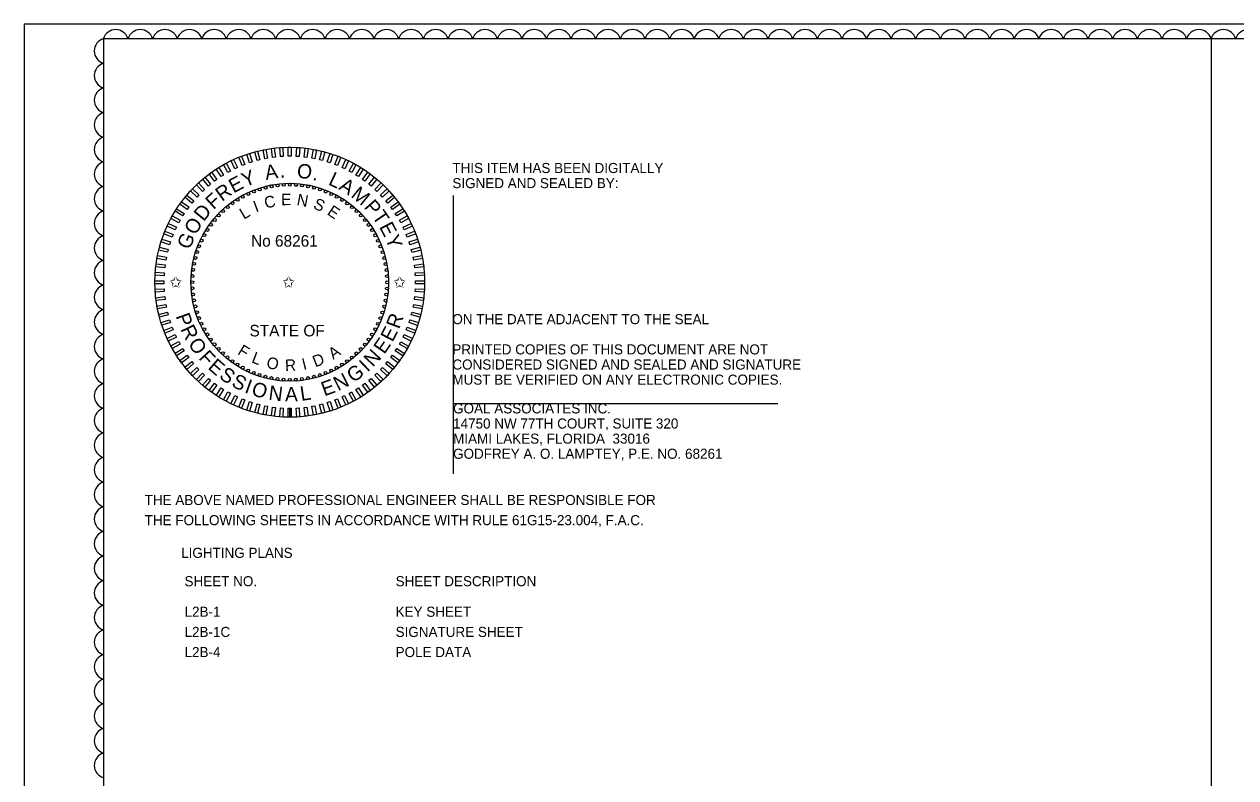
# Model space of a CAD drawing. Extents: x -811.3 to -790.1, y -2211.9 to -2188.9.
# Drawn here: x -811.34 to -802.91, y -2206.57 to -2201.34 of the extents above; entities that cross this region are included whole.
import ezdxf

# ---------------------------------------------------------------- set-up
doc = ezdxf.new("R2010")
doc.units = 0
for name, color, linetype in [('Cloud_dp', 7, 'Continuous'), ('Logo_dp', 7, 'Continuous'), ('NonPlottingEle_dp', 7, 'Continuous'), ('PlotBorder_dp', 7, 'Continuous'), ('ScratchEle_dp', 7, 'Continuous'), ('SheetBorder_dp', 7, 'Continuous'), ('TextMisc', 7, 'Continuous'), ('TextNotes', 7, 'Continuous')]:
    doc.layers.add(name, color=color, linetype=linetype)

msp = doc.modelspace()

# ---------------------------------------------------------------- linework, layer by layer
at = {"layer": 'Cloud_dp'}
for centre, start, end in [((-810.7002, -2201.467), 17.5, 162.5), ((-810.5291, -2201.467), 17.5, 162.5), ((-810.358, -2201.467), 17.5, 162.5), ((-810.1868, -2201.467), 17.5, 162.5), ((-810.0157, -2201.467), 17.5, 162.5), ((-809.8446, -2201.467), 17.5, 162.5), ((-809.6735, -2201.467), 17.5, 162.5), ((-809.5024, -2201.467), 17.5, 162.5), ((-809.3312, -2201.467), 17.5, 162.5), ((-809.1601, -2201.467), 17.5, 162.5), ((-808.989, -2201.467), 17.5, 162.5), ((-808.8179, -2201.467), 17.5, 162.5), ((-808.6467, -2201.467), 17.5, 162.5), ((-808.4756, -2201.467), 17.5, 162.5), ((-808.3045, -2201.467), 17.5, 162.5), ((-808.1334, -2201.467), 17.5, 162.5), ((-807.9622, -2201.467), 17.5, 162.5), ((-807.7911, -2201.467), 17.5, 162.5), ((-807.62, -2201.467), 17.5, 162.5), ((-807.4489, -2201.467), 17.5, 162.5), ((-807.2778, -2201.467), 17.5, 162.5), ((-807.1066, -2201.467), 17.5, 162.5), ((-806.9355, -2201.467), 17.5, 162.5), ((-806.7644, -2201.467), 17.5, 162.5), ((-806.5933, -2201.467), 17.5, 162.5), ((-806.4221, -2201.467), 17.5, 162.5), ((-806.251, -2201.467), 17.5, 162.5), ((-806.0799, -2201.467), 17.5, 162.5), ((-805.9088, -2201.467), 17.5, 162.5), ((-805.7377, -2201.467), 17.5, 162.5), ((-805.5665, -2201.467), 17.5, 162.5), ((-805.3954, -2201.467), 17.5, 162.5), ((-805.2243, -2201.467), 17.5, 162.5), ((-805.0532, -2201.467), 17.5, 162.5), ((-804.882, -2201.467), 17.5, 162.5), ((-804.7109, -2201.467), 17.5, 162.5), ((-804.5398, -2201.467), 17.5, 162.5), ((-804.3687, -2201.467), 17.5, 162.5), ((-804.1976, -2201.467), 17.5, 162.5), ((-804.0264, -2201.467), 17.5, 162.5), ((-803.8553, -2201.467), 17.5, 162.5), ((-803.6842, -2201.467), 17.5, 162.5), ((-803.5131, -2201.467), 17.5, 162.5), ((-803.3419, -2201.467), 17.5, 162.5), ((-803.1708, -2201.467), 17.5, 162.5), ((-802.9997, -2201.467), 17.5, 162.5), ((-802.8286, -2201.467), 17.5, 162.5), ((-810.7588, -2201.5256), 107.5, 252.5), ((-810.7588, -2201.6967), 107.5, 252.5), ((-810.7588, -2201.8679), 107.5, 252.5), ((-810.7588, -2202.039), 107.5, 252.5), ((-810.7588, -2202.2101), 107.5, 252.5), ((-810.7588, -2202.3812), 107.5, 252.5), ((-810.7588, -2202.5523), 107.5, 252.5), ((-810.7588, -2202.7235), 107.5, 252.5), ((-810.7588, -2202.8946), 107.5, 252.5), ((-810.7588, -2203.0657), 107.5, 252.5), ((-810.7588, -2203.2368), 107.5, 252.5), ((-810.7588, -2203.408), 107.5, 252.5), ((-810.7588, -2203.5791), 107.5, 252.5), ((-810.7588, -2203.7502), 107.5, 252.5), ((-810.7588, -2203.9213), 107.5, 252.5), ((-810.7588, -2204.0924), 107.5, 252.5), ((-810.7588, -2204.2636), 107.5, 252.5), ((-810.7588, -2204.4347), 107.5, 252.5), ((-810.7588, -2204.6058), 107.5, 252.5), ((-810.7588, -2204.7769), 107.5, 252.5), ((-810.7588, -2204.9481), 107.5, 252.5), ((-810.7588, -2205.1192), 107.5, 252.5), ((-810.7588, -2205.2903), 107.5, 252.5), ((-810.7588, -2205.4614), 107.5, 252.5), ((-810.7588, -2205.6326), 107.5, 252.5), ((-810.7588, -2205.8037), 107.5, 252.5), ((-810.7588, -2205.9748), 107.5, 252.5), ((-810.7588, -2206.1459), 107.5, 252.5), ((-810.7588, -2206.317), 107.5, 252.5), ((-810.7588, -2206.4882), 107.5, 252.5)]:
    msp.add_arc(centre, 0.0897, start, end, dxfattribs=at)
at = {"layer": 'Logo_dp'}
for p, q in [((-809.5001, -2204.0695), (-809.5003, -2204.007)), ((-809.4901, -2204.0695), (-809.4903, -2204.007)), ((-809.4801, -2204.0695), (-809.4803, -2204.007))]:
    msp.add_line(p, q, dxfattribs=at)
for points in [[(-809.8028, -2202.3147), (-809.8215, -2202.3221), (-809.8445, -2202.2641), (-809.8258, -2202.2566)], [(-809.7508, -2202.2967), (-809.77, -2202.3029), (-809.7893, -2202.2435), (-809.7701, -2202.2373)], [(-809.6979, -2202.2819), (-809.7174, -2202.287), (-809.7329, -2202.2265), (-809.7134, -2202.2215)], [(-809.6441, -2202.2706), (-809.6639, -2202.2743), (-809.6756, -2202.213), (-809.6558, -2202.2092)], [(-809.5897, -2202.2626), (-809.6097, -2202.2651), (-809.6175, -2202.2032), (-809.5975, -2202.2007)], [(-809.5349, -2202.2581), (-809.555, -2202.2593), (-809.559, -2202.197), (-809.5388, -2202.1957)], [(-809.4799, -2202.257), (-809.5001, -2202.257), (-809.5001, -2202.1945), (-809.4799, -2202.1945)], [(-809.425, -2202.2593), (-809.4452, -2202.2581), (-809.4412, -2202.1958), (-809.4211, -2202.197)], [(-809.3703, -2202.2652), (-809.3904, -2202.2626), (-809.3825, -2202.2007), (-809.3625, -2202.2032)], [(-809.3162, -2202.2744), (-809.336, -2202.2706), (-809.3243, -2202.2093), (-809.3045, -2202.2131)], [(-809.2626, -2202.287), (-809.2822, -2202.282), (-809.2667, -2202.2215), (-809.2471, -2202.2265)], [(-809.21, -2202.303), (-809.2292, -2202.2967), (-809.2099, -2202.2373), (-809.1907, -2202.2436)], [(-809.1585, -2202.3222), (-809.1773, -2202.3147), (-809.1543, -2202.2567), (-809.1355, -2202.2641)], [(-809.9504, -2202.3877), (-809.9674, -2202.3986), (-810.0009, -2202.3458), (-809.9838, -2202.335)], [(-809.9027, -2202.3603), (-809.9204, -2202.37), (-809.9505, -2202.3153), (-809.9328, -2202.3056)], [(-809.8535, -2202.3359), (-809.8717, -2202.3445), (-809.8983, -2202.288), (-809.8801, -2202.2794)], [(-809.1083, -2202.3446), (-809.1266, -2202.336), (-809.1, -2202.2795), (-809.0817, -2202.2881)], [(-809.0596, -2202.3701), (-809.0773, -2202.3604), (-809.0473, -2202.3057), (-809.0296, -2202.3154)], [(-809.0127, -2202.3987), (-809.0297, -2202.3878), (-808.9962, -2202.3351), (-808.9792, -2202.3459)], [(-810.04, -2202.4513), (-810.0556, -2202.4642), (-810.0954, -2202.416), (-810.0798, -2202.4032)], [(-809.9962, -2202.4181), (-810.0125, -2202.43), (-810.0492, -2202.3795), (-810.0329, -2202.3676)], [(-808.9676, -2202.4301), (-808.9839, -2202.4182), (-808.9472, -2202.3677), (-808.9308, -2202.3796)], [(-808.9245, -2202.4643), (-808.9401, -2202.4514), (-808.9003, -2202.4033), (-808.8847, -2202.4162)], [(-810.121, -2202.5256), (-810.1348, -2202.5403), (-810.1804, -2202.4976), (-810.1665, -2202.4828)], [(-810.0817, -2202.4872), (-810.0964, -2202.501), (-810.1392, -2202.4555), (-810.1244, -2202.4416)], [(-808.8837, -2202.5011), (-808.8984, -2202.4873), (-808.8557, -2202.4418), (-808.841, -2202.4556)], [(-808.8453, -2202.5404), (-808.8591, -2202.5257), (-808.8136, -2202.483), (-808.7998, -2202.4977)], [(-810.192, -2202.6094), (-810.2039, -2202.6258), (-810.2544, -2202.5891), (-810.2426, -2202.5727)], [(-810.1579, -2202.5664), (-810.1707, -2202.5819), (-810.2188, -2202.5421), (-810.206, -2202.5266)], [(-808.8094, -2202.5821), (-808.8223, -2202.5665), (-808.7742, -2202.5267), (-808.7613, -2202.5423)], [(-808.7762, -2202.6259), (-808.7881, -2202.6096), (-808.7376, -2202.5729), (-808.7257, -2202.5892)], [(-810.252, -2202.7015), (-810.2617, -2202.7192), (-810.3164, -2202.6891), (-810.3067, -2202.6715)], [(-810.2235, -2202.6545), (-810.2343, -2202.6716), (-810.287, -2202.6381), (-810.2762, -2202.6211)], [(-808.7459, -2202.6717), (-808.7567, -2202.6547), (-808.7039, -2202.6212), (-808.6931, -2202.6383)], [(-808.7184, -2202.7194), (-808.7281, -2202.7017), (-808.6734, -2202.6716), (-808.6637, -2202.6893)], [(-810.2775, -2202.7502), (-810.2861, -2202.7685), (-810.3426, -2202.7419), (-810.334, -2202.7236)], [(-808.694, -2202.7687), (-808.7026, -2202.7504), (-808.6461, -2202.7238), (-808.6375, -2202.7421)], [(-810.3192, -2202.8519), (-810.3254, -2202.8711), (-810.3848, -2202.8518), (-810.3786, -2202.8326)], [(-810.3, -2202.8004), (-810.3074, -2202.8192), (-810.3654, -2202.7962), (-810.358, -2202.7774)], [(-808.6728, -2202.8194), (-808.6802, -2202.8006), (-808.6222, -2202.7776), (-808.6147, -2202.7964)], [(-808.6548, -2202.8713), (-808.661, -2202.8521), (-808.6016, -2202.8328), (-808.5954, -2202.852)], [(-810.3351, -2202.9045), (-810.3401, -2202.9241), (-810.4006, -2202.9086), (-810.3956, -2202.889)], [(-808.64, -2202.9243), (-808.6451, -2202.9047), (-808.5846, -2202.8892), (-808.5796, -2202.9087)], [(-810.357, -2203.0122), (-810.3595, -2203.0323), (-810.4215, -2203.0244), (-810.4189, -2203.0044)], [(-810.3477, -2202.958), (-810.3515, -2202.9779), (-810.4129, -2202.9662), (-810.4091, -2202.9463)], [(-808.6287, -2202.978), (-808.6325, -2202.9582), (-808.5711, -2202.9465), (-808.5673, -2202.9663)], [(-808.6207, -2203.0324), (-808.6232, -2203.0124), (-808.5613, -2203.0046), (-808.5588, -2203.0246)], [(-810.3628, -2203.0669), (-810.3641, -2203.087), (-810.4264, -2203.0831), (-810.4251, -2203.063)], [(-808.6162, -2203.0872), (-808.6174, -2203.0671), (-808.5551, -2203.0632), (-808.5539, -2203.0833)], [(-810.3652, -2203.1218), (-810.3652, -2203.142), (-810.4276, -2203.142), (-810.4276, -2203.1218)], [(-810.3641, -2203.1768), (-810.3628, -2203.1969), (-810.4251, -2203.2009), (-810.4264, -2203.1807)], [(-808.6175, -2203.1971), (-808.6162, -2203.177), (-808.5539, -2203.1809), (-808.5551, -2203.201)], [(-808.6151, -2203.1422), (-808.6151, -2203.122), (-808.5527, -2203.122), (-808.5527, -2203.1422)], [(-810.3595, -2203.2316), (-810.357, -2203.2516), (-810.4189, -2203.2594), (-810.4215, -2203.2394)], [(-808.6233, -2203.2518), (-808.6207, -2203.2318), (-808.5588, -2203.2396), (-808.5613, -2203.2596)], [(-810.3516, -2203.286), (-810.3478, -2203.3058), (-810.4091, -2203.3175), (-810.4129, -2203.2977)], [(-810.3402, -2203.3398), (-810.3352, -2203.3593), (-810.3957, -2203.3748), (-810.4007, -2203.3553)], [(-808.6451, -2203.3595), (-808.6401, -2203.3399), (-808.5796, -2203.3555), (-808.5846, -2203.375)], [(-808.6325, -2203.306), (-808.6287, -2203.2861), (-808.5674, -2203.2978), (-808.5712, -2203.3177)], [(-810.3255, -2203.3927), (-810.3192, -2203.4119), (-810.3786, -2203.4312), (-810.3849, -2203.412)], [(-808.6611, -2203.4121), (-808.6548, -2203.3929), (-808.5954, -2203.4122), (-808.6017, -2203.4314)], [(-810.3075, -2203.4447), (-810.3, -2203.4634), (-810.3581, -2203.4864), (-810.3655, -2203.4676)], [(-810.2862, -2203.4954), (-810.2776, -2203.5136), (-810.3341, -2203.5402), (-810.3427, -2203.5219)], [(-808.7027, -2203.5138), (-808.6941, -2203.4955), (-808.6376, -2203.5221), (-808.6462, -2203.5404)], [(-808.6803, -2203.4636), (-808.6729, -2203.4448), (-808.6148, -2203.4678), (-808.6222, -2203.4866)], [(-810.2618, -2203.5446), (-810.2521, -2203.5623), (-810.3068, -2203.5924), (-810.3165, -2203.5747)], [(-810.2344, -2203.5923), (-810.2236, -2203.6093), (-810.2763, -2203.6428), (-810.2871, -2203.6257)], [(-808.7568, -2203.6095), (-808.746, -2203.5924), (-808.6932, -2203.6259), (-808.704, -2203.6429)], [(-808.7282, -2203.5625), (-808.7185, -2203.5448), (-808.6638, -2203.5749), (-808.6735, -2203.5926)], [(-810.204, -2203.6381), (-810.1922, -2203.6544), (-810.2427, -2203.6911), (-810.2545, -2203.6748)], [(-810.1708, -2203.6819), (-810.158, -2203.6975), (-810.2061, -2203.7373), (-810.2189, -2203.7217)], [(-808.8224, -2203.6976), (-808.8095, -2203.6821), (-808.7614, -2203.7219), (-808.7743, -2203.7374)], [(-808.7882, -2203.6546), (-808.7763, -2203.6382), (-808.7258, -2203.6749), (-808.7377, -2203.6913)], [(-810.135, -2203.7236), (-810.1211, -2203.7383), (-810.1667, -2203.781), (-810.1805, -2203.7663)], [(-810.0965, -2203.7629), (-810.0818, -2203.7767), (-810.1246, -2203.8222), (-810.1393, -2203.8084)], [(-808.8985, -2203.7768), (-808.8838, -2203.763), (-808.8411, -2203.8085), (-808.8558, -2203.8224)], [(-808.8592, -2203.7384), (-808.8454, -2203.7237), (-808.7999, -2203.7665), (-808.8137, -2203.7812)], [(-810.0557, -2203.7997), (-810.0402, -2203.8126), (-810.08, -2203.8607), (-810.0955, -2203.8478)], [(-810.0127, -2203.8339), (-809.9964, -2203.8458), (-810.0331, -2203.8963), (-810.0494, -2203.8844)], [(-808.984, -2203.8459), (-808.9677, -2203.834), (-808.931, -2203.8846), (-808.9473, -2203.8964)], [(-808.9402, -2203.8127), (-808.9247, -2203.7999), (-808.8848, -2203.848), (-808.9004, -2203.8608)], [(-809.9676, -2203.8654), (-809.9505, -2203.8762), (-809.984, -2203.9289), (-810.001, -2203.9181)], [(-809.9206, -2203.8939), (-809.9029, -2203.9036), (-809.933, -2203.9583), (-809.9507, -2203.9486)], [(-809.8719, -2203.9194), (-809.8536, -2203.928), (-809.8802, -2203.9845), (-809.8985, -2203.9759)], [(-809.1268, -2203.9281), (-809.1085, -2203.9195), (-809.0819, -2203.976), (-809.1002, -2203.9846)], [(-809.0775, -2203.9037), (-809.0598, -2203.894), (-809.0297, -2203.9487), (-809.0474, -2203.9584)], [(-809.0299, -2203.8763), (-809.0128, -2203.8655), (-808.9794, -2203.9182), (-808.9964, -2203.929)], [(-809.8217, -2203.9418), (-809.8029, -2203.9493), (-809.8259, -2204.0073), (-809.8447, -2203.9999)], [(-809.7702, -2203.9611), (-809.751, -2203.9673), (-809.7703, -2204.0267), (-809.7895, -2204.0204)], [(-809.7176, -2203.977), (-809.698, -2203.982), (-809.7136, -2204.0425), (-809.7331, -2204.0375)], [(-809.6641, -2203.9896), (-809.6443, -2203.9934), (-809.656, -2204.0547), (-809.6758, -2204.051)], [(-809.6099, -2203.9989), (-809.5899, -2204.0014), (-809.5977, -2204.0633), (-809.6177, -2204.0608)], [(-809.5552, -2204.0047), (-809.5351, -2204.0059), (-809.539, -2204.0683), (-809.5592, -2204.067)], [(-809.5003, -2204.007), (-809.4801, -2204.007), (-809.4801, -2204.0695), (-809.5003, -2204.0695)], [(-809.4453, -2204.0059), (-809.4252, -2204.0047), (-809.4213, -2204.067), (-809.4414, -2204.0683)], [(-809.3906, -2204.0014), (-809.3705, -2203.9989), (-809.3627, -2204.0608), (-809.3827, -2204.0634)], [(-809.3362, -2203.9934), (-809.3163, -2203.9897), (-809.3046, -2204.051), (-809.3245, -2204.0548)], [(-809.2824, -2203.9821), (-809.2628, -2203.9771), (-809.2473, -2204.0375), (-809.2668, -2204.0426)], [(-809.2294, -2203.9674), (-809.2102, -2203.9611), (-809.1909, -2204.0205), (-809.2101, -2204.0267)], [(-809.1775, -2203.9493), (-809.1587, -2203.9419), (-809.1357, -2204), (-809.1545, -2204.0074)]]:
    msp.add_lwpolyline(points, close=True, dxfattribs=at)
for centre in [(-809.7781, -2202.5188), (-809.739, -2202.5019), (-809.6989, -2202.4875), (-809.6581, -2202.4757), (-809.6165, -2202.4664), (-809.5745, -2202.4598), (-809.5321, -2202.4558), (-809.4896, -2202.4545), (-809.447, -2202.4559), (-809.4047, -2202.46), (-809.3626, -2202.4666), (-809.3211, -2202.476), (-809.2802, -2202.4879), (-809.2402, -2202.5023), (-809.2012, -2202.5193), (-809.8879, -2202.5836), (-809.8527, -2202.5597), (-809.816, -2202.5381), (-809.1633, -2202.5386), (-809.1266, -2202.5603), (-809.0915, -2202.5843), (-809.9836, -2202.6678), (-809.9535, -2202.6378), (-809.9215, -2202.6096), (-809.0579, -2202.6104), (-809.026, -2202.6385), (-808.9959, -2202.6687), (-810.0618, -2202.7685), (-810.0379, -2202.7333), (-810.0118, -2202.6997), (-808.9678, -2202.7006), (-808.9417, -2202.7343), (-808.9178, -2202.7695), (-810.1029, -2202.843), (-810.0835, -2202.8051), (-808.8962, -2202.8061), (-808.8769, -2202.8441), (-810.1343, -2202.9221), (-810.1198, -2202.8821), (-808.86, -2202.8831), (-808.8456, -2202.9232), (-810.1555, -2203.0045), (-810.1462, -2202.963), (-808.8338, -2202.9641), (-808.8245, -2203.0056), (-810.1662, -2203.0889), (-810.1622, -2203.0465), (-808.8179, -2203.0477), (-808.814, -2203.09), (-810.1676, -2203.1314), (-810.1663, -2203.174), (-808.814, -2203.1751), (-808.8127, -2203.1326), (-810.1623, -2203.2164), (-810.1557, -2203.2584), (-808.8248, -2203.2595), (-808.8181, -2203.2175), (-810.1464, -2203.2999), (-810.1346, -2203.3408), (-808.846, -2203.3419), (-808.8341, -2203.301), (-810.1202, -2203.3809), (-810.1034, -2203.4199), (-808.8774, -2203.421), (-808.8604, -2203.3819), (-810.0841, -2203.4579), (-810.0624, -2203.4945), (-810.0385, -2203.5298), (-808.9184, -2203.4955), (-808.8967, -2203.4589), (-810.0125, -2203.5634), (-809.9844, -2203.5954), (-808.9967, -2203.5962), (-808.9685, -2203.5643), (-808.9424, -2203.5307), (-809.9543, -2203.6255), (-809.9224, -2203.6536), (-809.8888, -2203.6798), (-809.0924, -2203.6804), (-809.0587, -2203.6544), (-809.0268, -2203.6262), (-809.8536, -2203.7037), (-809.817, -2203.7254), (-809.7791, -2203.7448), (-809.74, -2203.7617), (-809.7, -2203.7761), (-809.2813, -2203.7765), (-809.2413, -2203.7621), (-809.2022, -2203.7452), (-809.1642, -2203.7259), (-809.1276, -2203.7043), (-809.6591, -2203.7881), (-809.6176, -2203.7974), (-809.5756, -2203.8041), (-809.5332, -2203.8081), (-809.4901, -2203.8095), (-809.4481, -2203.8082), (-809.4058, -2203.8042), (-809.3637, -2203.7976), (-809.3222, -2203.7883)]:
    msp.add_circle(centre, 0.01, dxfattribs=at)
at = {"layer": 'NonPlottingEle_dp'}
for radius in [0.9375, 0.6875]:
    msp.add_circle((-809.4901, -2203.132), radius, dxfattribs=at)
at = {"layer": 'PlotBorder_dp'}
msp.add_lwpolyline([(-811.3358, -2211.9401), (-794.8358, -2211.9401), (-794.8358, -2201.3401), (-811.3358, -2201.3401)], close=True, dxfattribs=at)
at = {"layer": 'ScratchEle_dp'}
for p, q in [((-808.3546, -2202.5286), (-808.3546, -2204.4633)), ((-808.3546, -2203.9733), (-806.0979, -2203.9733))]:
    msp.add_line(p, q, dxfattribs=at)
at = {"layer": 'SheetBorder_dp'}
for p, q in [((-810.7858, -2201.4401), (-810.7858, -2211.8401)), ((-810.7858, -2201.4401), (-795.3858, -2201.4401)), ((-803.0858, -2201.4401), (-803.0858, -2211.0401))]:
    msp.add_line(p, q, dxfattribs=at)

# ---------------------------------------------------------------- texts
at = {"layer": 'Logo_dp'}
for s, height, rotation, p in [('A', 0.1, 8.80884, (-809.6551, -2202.4214)), ('O', 0.1, 352.18771, (-809.4449, -2202.4039)), ('E', 0.1, 28.10553, (-809.8806, -2202.5158)), ('Y', 0.1, 21.06329, (-809.8021, -2202.4726)), ('.', 0.1, 1.04184, (-809.5575, -2202.4056)), ('.', 0.1, 343.52684, (-809.3358, -2202.419)), ('L', 0.1, 334.67271, (-809.2279, -2202.4513)), ('A', 0.1, 328.40959, (-809.1552, -2202.4839)), ('F', 0.1, 42.37723, (-810.0205, -2202.6311)), ('R', 0.1, 35.92688, (-809.9609, -2202.5747)), ('M', 0.1, 320.6426, (-809.0707, -2202.5351)), ('I', 0.08, 20.01168, (-809.7258, -2202.6479)), ('C', 0.08, 12.20255, (-809.6579, -2202.6204)), ('E', 0.08, 0.41861, (-809.5498, -2202.5969)), ('N', 0.08, 349.29143, (-809.4455, -2202.5955)), ('S', 0.08, 337.02207, (-809.3325, -2202.6172)), ('P', 0.1, 311.19658, (-808.9784, -2202.6121)), ('D', 0.1, 50.8569, (-810.0886, -2202.7148)), ('L', 0.08, 30.40215, (-809.8093, -2202.6984)), ('E', 0.08, 325.86633, (-809.2358, -2202.6574)), ('T', 0.1, 304.45632, (-808.9209, -2202.6757)), ('O', 0.1, 59.51777, (-810.1446, -2202.8097)), ('E', 0.1, 297.63152, (-808.8707, -2202.7466)), ('G', 0.1, 68.0518, (-810.1851, -2202.9103)), ('Y', 0.1, 290.58928, (-808.8281, -2202.8255)), ('P', 0.1, 289.40551, (-810.2848, -2203.3666)), ('R', 0.1, 69.5134, (-808.7299, -2203.4617)), ('R', 0.1, 296.14576, (-810.2518, -2203.4582)), ('E', 0.1, 62.47116, (-808.7761, -2203.5524)), ('E', 0.1, 55.42892, (-808.833, -2203.6368)), ('O', 0.1, 303.96711, (-810.2003, -2203.5589)), ('F', 0.1, 312.62798, (-810.1279, -2203.6609)), ('F', 0.08, 328.72408, (-809.8582, -2203.6286)), ('A', 0.08, 34.49917, (-809.1883, -2203.6714)), ('N', 0.1, 47.17876, (-808.9123, -2203.7259)), ('E', 0.1, 319.07833, (-810.0645, -2203.7292)), ('L', 0.08, 339.29159, (-809.7609, -2203.6877)), ('O', 0.08, 349.68206, (-809.6562, -2203.7274)), ('R', 0.08, 2.33977, (-809.5217, -2203.7493)), ('I', 0.08, 14.20366, (-809.3941, -2203.7426)), ('D', 0.08, 22.01279, (-809.312, -2203.7239)), ('I', 0.1, 43.64556, (-808.9499, -2203.7603)), ('S', 0.1, 326.12056, (-809.9869, -2203.7952)), ('N', 0.1, 26.86136, (-809.1544, -2203.8896)), ('G', 0.1, 35.11153, (-809.0492, -2203.8335)), ('S', 0.1, 333.193, (-809.9015, -2203.8513)), ('I', 0.1, 340.26543, (-809.8098, -2203.8965)), ('O', 0.1, 343.79863, (-809.7621, -2203.9147)), ('N', 0.1, 352.45949, (-809.6411, -2203.9467)), ('L', 0.1, 8.47665, (-809.4105, -2203.9568)), ('E', 0.1, 19.81912, (-809.2498, -2203.925)), ('A', 0.1, 0.70966, (-809.5227, -2203.96))]:
    msp.add_text(s, height=height, rotation=rotation, dxfattribs=at).set_placement(p)
for s, p in [('No 68261', (-809.7591, -2202.8848)), ('✩', (-810.3251, -2203.17)), ('✩', (-809.5404, -2203.17)), ('✩', (-808.7685, -2203.17)), ('STATE OF', (-809.7698, -2203.5082))]:
    msp.add_text(s, height=0.08, dxfattribs=at).set_placement(p)
at = {"layer": 'TextMisc'}
for s, p in [('THIS ITEM HAS BEEN DIGITALLY', (-808.3596, -2202.3735)), ('SIGNED AND SEALED BY:', (-808.3596, -2202.4785)), ('ON THE DATE ADJACENT TO THE SEAL', (-808.3596, -2203.4235)), ('PRINTED COPIES OF THIS DOCUMENT ARE NOT ', (-808.3596, -2203.6335)), ('CONSIDERED SIGNED AND SEALED AND SIGNATURE ', (-808.3596, -2203.7385)), ('MUST BE VERIFIED ON ANY ELECTRONIC COPIES.', (-808.3596, -2203.8435)), ('GOAL ASSOCIATES INC.', (-808.3546, -2204.0433)), ('14750 NW 77TH COURT, SUITE 320', (-808.3546, -2204.1483)), ('MIAMI LAKES, FLORIDA  33016', (-808.3546, -2204.2533)), ('GODFREY A. O. LAMPTEY, P.E. NO. 68261', (-808.3546, -2204.3583)), ('THE ABOVE NAMED PROFESSIONAL ENGINEER SHALL BE RESPONSIBLE FOR ', (-810.4987, -2204.6794)), ('THE FOLLOWING SHEETS IN ACCORDANCE WITH RULE 61G15-23.004, F.A.C.', (-810.4987, -2204.8194)), ('LIGHTING PLANS', (-810.245, -2205.0465))]:
    msp.add_text(s, height=0.07, dxfattribs=at).set_placement(p)
at = {"layer": 'TextNotes'}
for s, p in [('SHEET NO.', (-810.2215, -2205.2435)), ('SHEET DESCRIPTION', (-808.7542, -2205.2435)), ('L2B-1', (-810.2215, -2205.4557)), ('KEY SHEET', (-808.7542, -2205.4557)), ('L2B-1C', (-810.2215, -2205.5957)), ('SIGNATURE SHEET', (-808.7542, -2205.5957)), ('L2B-4 ', (-810.2215, -2205.7357)), ('POLE DATA', (-808.7542, -2205.7357))]:
    msp.add_text(s, height=0.07, dxfattribs=at).set_placement(p)

doc.saveas('drawing.dxf')
